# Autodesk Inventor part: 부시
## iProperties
IsCustomPart: 1
Created: 2009-02
Part Number: 부시
Material: 강, 연강
Description: 압력 맞춤 부시 - 머리 있는 유형
Document SubType Name: Modeling
Standard: ISO 4247
Designer: KYOUNG IL JANG
Standard Revision: 1판 1977-12-15
Standards Organization: ISO
Language: ko-KR
Size Designation: 15
Categories: <MemberInstance><Categories><Category DisplayName="기타 부품" InternalName="5aa15e00-363f-49f2-933f-16f664388e3f" Mnemonic="OTHER"><Category DisplayName="드릴 부싱" Int
Density: 7.86 g/cm^3
Mass: 62.5871 g
Surface Area: 38.4072 cm^2
Volume: 7.96273 cm^3
Author: KYOUNG IL JANG
